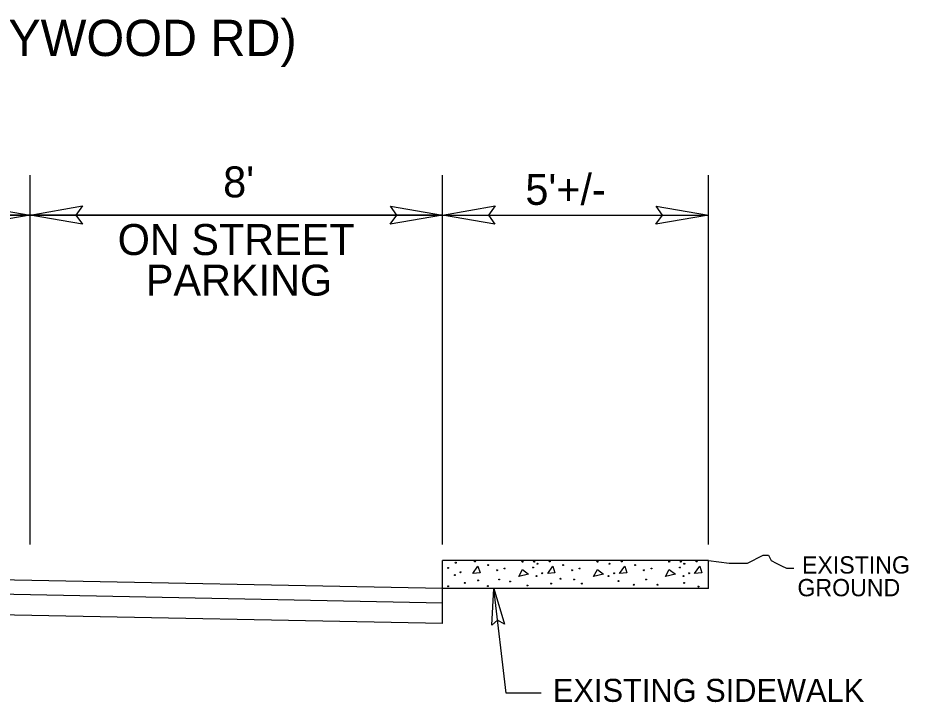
# Model space of a CAD drawing. Extents: x 1022283 to 1026986, y 174822 to 180471.
# Drawn here: x 1024095.7 to 1024555.8, y 178453.3 to 178807 of the extents above; entities that cross this region are included whole.
import ezdxf

# ---------------------------------------------------------------- set-up
doc = ezdxf.new("R2010")
doc.units = 0
for name, color, linetype in [('Default', 7, 'Continuous'), ('Prop Dimension', 7, 'Continuous'), ('Prop Terminator CELL', 7, 'Continuous'), ('Typical Curb CELL', 7, 'Continuous'), ('Typical Slope Point Local CELL', 7, 'Continuous'), ('Typical Text General CELL', 7, 'Continuous')]:
    doc.layers.add(name, color=color, linetype=linetype)

# ---------------------------------------------------------------- blocks, each defined once
blk = doc.blocks.new('Terminator')
at = {"layer": 'Prop Terminator CELL'}
blk.add_lwpolyline([(-9, 1.55), (0, 0), (-9.05, -1.6), (-7.9, 0)], close=True, dxfattribs=at)

msp = doc.modelspace()

# ---------------------------------------------------------------- linework, layer by layer
at = {"layer": 'Default'}
for p, q in [((1024102.03, 178534.78), (1024102.03, 178725.6)), ((1024315.21, 178534.78), (1024315.21, 178725.6)), ((1024452.59, 178534.78), (1024452.59, 178725.6)), ((1023807.5, 178705.04), (1024315.21, 178705.04)), ((1024315.21, 178705.04), (1023807.5, 178705.04)), ((1024102.03, 178705.04), (1024315.21, 178705.04)), ((1024315.21, 178705.04), (1024452.59, 178705.04))]:
    msp.add_line(p, q, dxfattribs=at)
at = {"layer": 'Prop Dimension'}
for p, q in [((1024315.21, 178511.99), (1023807.5, 178522.14)), ((1024315.21, 178511.99), (1023807.5, 178522.14)), ((1024315.21, 178504.49), (1023807.5, 178514.64)), ((1024315.21, 178504.49), (1023807.5, 178514.64)), ((1024348.01, 178457.9), (1024341.76, 178511.99)), ((1024315.21, 178493.9), (1023807.5, 178504.06)), ((1024366.16, 178457.9), (1024348.01, 178457.9))]:
    msp.add_line(p, q, dxfattribs=at)
at = {"layer": 'Prop Terminator CELL'}
for points in [[(1024075.03, 178709.69), (1024102.03, 178705.04), (1024074.88, 178700.24), (1024078.33, 178705.04)], [(1024129.03, 178700.39), (1024102.03, 178705.04), (1024129.18, 178709.84), (1024125.73, 178705.04)], [(1024288.21, 178709.69), (1024315.21, 178705.04), (1024288.06, 178700.24), (1024291.51, 178705.04)], [(1024342.21, 178700.39), (1024315.21, 178705.04), (1024342.36, 178709.84), (1024338.91, 178705.04)], [(1024425.59, 178709.69), (1024452.59, 178705.04), (1024425.44, 178700.24), (1024428.89, 178705.04)]]:
    msp.add_lwpolyline(points, close=True, dxfattribs=at)
at = {"layer": 'Typical Curb CELL'}
for p, q in [((1024315.21, 178495.51), (1024315.21, 178526.52)), ((1024315.21, 178516.18), (1024315.21, 178526.52)), ((1024315.21, 178516.18), (1024315.21, 178526.52)), ((1024452.59, 178526.52), (1024315.21, 178526.52)), ((1024315.21, 178493.91), (1024315.21, 178526.52)), ((1024315.21, 178495.51), (1024315.21, 178526.52)), ((1024315.21, 178516.18), (1024315.21, 178526.52)), ((1024315.21, 178516.18), (1024315.21, 178526.52)), ((1024452.59, 178526.52), (1024315.21, 178526.52)), ((1024315.21, 178493.91), (1024315.21, 178526.52)), ((1024452.59, 178511.99), (1024452.59, 178526.52)), ((1024452.59, 178511.99), (1024452.59, 178526.52)), ((1024330.79, 178519.88), (1024333.47, 178523.6)), ((1024330.79, 178519.88), (1024333.47, 178523.6)), ((1024334.54, 178520.08), (1024330.79, 178519.88)), ((1024334.54, 178520.08), (1024330.79, 178519.88)), ((1024333.47, 178523.6), (1024334.54, 178520.08)), ((1024333.47, 178523.6), (1024334.54, 178520.08)), ((1024354.53, 178518.3), (1024356.47, 178521.85)), ((1024354.53, 178518.3), (1024356.47, 178521.85)), ((1024356.47, 178521.85), (1024359.66, 178519.53)), ((1024356.47, 178521.85), (1024359.66, 178519.53)), ((1024369.55, 178519.88), (1024372.19, 178523.6)), ((1024369.55, 178519.88), (1024372.19, 178523.6)), ((1024373.26, 178520.08), (1024369.55, 178519.88)), ((1024373.26, 178520.08), (1024369.55, 178519.88)), ((1024372.19, 178523.6), (1024373.26, 178520.08)), ((1024372.19, 178523.6), (1024373.26, 178520.08)), ((1024393.25, 178518.3), (1024395.19, 178521.85)), ((1024393.25, 178518.3), (1024395.19, 178521.85)), ((1024395.19, 178521.85), (1024398.39, 178519.53)), ((1024395.19, 178521.85), (1024398.39, 178519.53)), ((1024406.68, 178519.88), (1024409.36, 178523.6)), ((1024406.68, 178519.88), (1024409.36, 178523.6)), ((1024410.43, 178520.08), (1024406.68, 178519.88)), ((1024410.43, 178520.08), (1024406.68, 178519.88)), ((1024409.36, 178523.6), (1024410.43, 178520.08)), ((1024409.36, 178523.6), (1024410.43, 178520.08)), ((1024430.42, 178518.3), (1024432.36, 178521.85)), ((1024430.42, 178518.3), (1024432.36, 178521.85)), ((1024432.36, 178521.85), (1024435.55, 178519.53)), ((1024432.36, 178521.85), (1024435.55, 178519.53)), ((1024445.44, 178519.88), (1024448.08, 178523.6)), ((1024445.44, 178519.88), (1024448.08, 178523.6)), ((1024449.15, 178520.08), (1024445.44, 178519.88)), ((1024449.15, 178520.08), (1024445.44, 178519.88)), ((1024448.08, 178523.6), (1024449.15, 178520.08)), ((1024448.08, 178523.6), (1024449.15, 178520.08)), ((1024359.66, 178519.53), (1024354.53, 178518.3)), ((1024359.66, 178519.53), (1024354.53, 178518.3)), ((1024398.39, 178519.53), (1024393.25, 178518.3)), ((1024398.39, 178519.53), (1024393.25, 178518.3)), ((1024435.55, 178519.53), (1024430.42, 178518.3)), ((1024435.55, 178519.53), (1024430.42, 178518.3)), ((1024452.59, 178511.99), (1024315.21, 178511.99))]:
    msp.add_line(p, q, dxfattribs=at)
for centre in [(1024322.01, 178525.4), (1024322.01, 178525.4), (1024331.87, 178526.09), (1024331.87, 178526.09), (1024356.47, 178525.92), (1024356.47, 178525.92), (1024362.49, 178525.92), (1024362.49, 178525.92), (1024364.23, 178524.86), (1024364.23, 178524.86), (1024370.6, 178526.09), (1024370.6, 178526.09), (1024395.21, 178525.92), (1024395.21, 178525.92), (1024401.38, 178524.86), (1024401.38, 178524.86), (1024407.76, 178526.09), (1024407.76, 178526.09), (1024432.36, 178525.92), (1024432.36, 178525.92), (1024438.38, 178525.92), (1024438.38, 178525.92), (1024440.12, 178524.86), (1024440.12, 178524.86), (1024446.49, 178526.09), (1024446.49, 178526.09), (1024318.07, 178522.71), (1024318.07, 178522.71), (1024324.5, 178520.44), (1024324.5, 178520.44), (1024338.77, 178524.15), (1024338.77, 178524.15), (1024343.38, 178521.49), (1024343.38, 178521.49), (1024347.27, 178522.38), (1024347.27, 178522.38), (1024361.96, 178522.91), (1024361.96, 178522.91), (1024366.71, 178519.9), (1024366.71, 178519.9), (1024377.51, 178524.15), (1024377.51, 178524.15), (1024382.11, 178521.49), (1024382.11, 178521.49), (1024386.01, 178522.38), (1024386.01, 178522.38), (1024403.87, 178519.9), (1024403.87, 178519.9), (1024414.66, 178524.15), (1024414.66, 178524.15), (1024419.27, 178521.49), (1024419.27, 178521.49), (1024423.16, 178522.38), (1024423.16, 178522.38), (1024437.85, 178522.91), (1024437.85, 178522.91), (1024442.6, 178519.9), (1024442.6, 178519.9), (1024321.52, 178519.02), (1024321.52, 178519.02), (1024333.51, 178516.25), (1024333.51, 178516.25), (1024344.43, 178516.71), (1024344.43, 178516.71), (1024350.05, 178515.67), (1024350.05, 178515.67), (1024363.73, 178518.48), (1024363.73, 178518.48), (1024376.21, 178517.09), (1024376.21, 178517.09), (1024383.17, 178516.71), (1024383.17, 178516.71), (1024400.89, 178518.48), (1024400.89, 178518.48), (1024406.11, 178515.86), (1024406.11, 178515.86), (1024420.32, 178516.71), (1024420.32, 178516.71), (1024439.62, 178518.48), (1024439.62, 178518.48), (1024318.07, 178513.21), (1024318.07, 178513.21), (1024326.67, 178514.95), (1024326.67, 178514.95), (1024338.62, 178513.34), (1024338.62, 178513.34), (1024359.03, 178513.6), (1024359.03, 178513.6), (1024371.23, 178514.57), (1024371.23, 178514.57), (1024387.19, 178514.57), (1024387.19, 178514.57), (1024414, 178513.99), (1024414, 178513.99), (1024426.27, 178513.99), (1024426.27, 178513.99), (1024439.96, 178514.95), (1024439.96, 178514.95), (1024447.39, 178513.02), (1024447.39, 178513.02)]:
    msp.add_circle(centre, 0.249, dxfattribs=at)
at = {"layer": 'Typical Slope Point Local CELL'}
msp.add_lwpolyline([(1024452.59, 178526.52), (1024463.36, 178525.17), (1024466.05, 178525.17), (1024470.1, 178525.17), (1024472.79, 178525.17), (1024475.48, 178526.52), (1024478.18, 178527.87), (1024480.87, 178529.22), (1024483.56, 178529.22), (1024484.91, 178526.52), (1024487.61, 178525.17), (1024490.3, 178523.82), (1024492.99, 178522.48), (1024495.69, 178522.48), (1024496.75, 178522.48)], dxfattribs=at)
msp.add_lwpolyline([(1024452.59, 178526.52), (1024463.36, 178525.17), (1024466.05, 178525.17), (1024470.1, 178525.17), (1024472.79, 178525.17), (1024475.48, 178526.52), (1024478.18, 178527.87), (1024480.87, 178529.22), (1024483.56, 178529.22), (1024484.91, 178526.52), (1024487.61, 178525.17), (1024490.3, 178523.82), (1024492.99, 178522.48), (1024495.69, 178522.48), (1024496.75, 178522.48)], dxfattribs=at)

# ---------------------------------------------------------------- block references
at = {"layer": 'Prop Dimension', "xscale": 2.0767499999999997, "yscale": 2.076749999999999, "rotation": 96.5883266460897}
msp.add_blockref('Terminator', (1024341.76, 178511.99), dxfattribs=at)

# ---------------------------------------------------------------- texts
at = {"layer": 'Prop Dimension'}
for s, height, p in [('-EL- US 19/23 BUS (HAYWOOD RD) ', 18.75, (1023823.22, 178787.21)), ("8'", 16, (1024201.8, 178714.17)), ("5'+/-", 16, (1024357.97, 178710.3)), ('ON STREET', 16, (1024147.3, 178684.38)), ('PARKING', 16, (1024161.84, 178663.4))]:
    msp.add_text(s, height=height, dxfattribs=at).set_placement(p)
at = {"layer": 'Typical Slope Point Local CELL'}
for s, p in [('EXISTING ', (1024500.91, 178519.76)), ('EXISTING ', (1024500.91, 178519.76)), ('GROUND', (1024498.58, 178508.04)), ('GROUND', (1024498.58, 178508.04))]:
    msp.add_text(s, height=8.938, dxfattribs=at).set_placement(p)
at = {"layer": 'Typical Text General CELL'}
msp.add_text('EXISTING SIDEWALK', height=11.8979, dxfattribs=at).set_placement((1024372.2, 178453.47))

doc.saveas('drawing.dxf')
